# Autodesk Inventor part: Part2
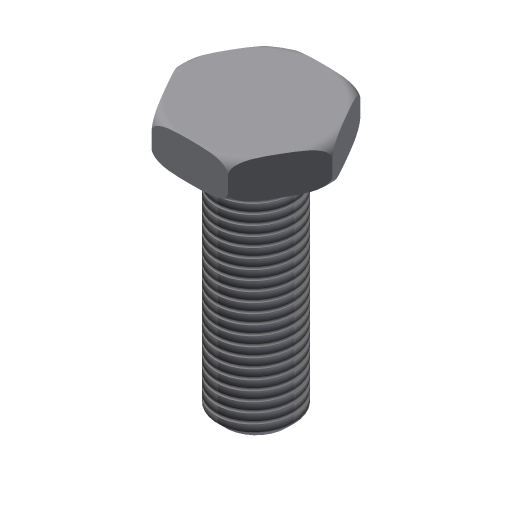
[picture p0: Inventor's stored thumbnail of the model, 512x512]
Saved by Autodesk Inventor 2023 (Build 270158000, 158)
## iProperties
Created: 2002-01
Part Number: Part2
Document SubType Name: Modeling
Designer: ***
Density: 1 g/cm^3
Material: Generic
Appearance: Default
Control State: 0
Master: False
Checked Out: False
Shininess: 77.0
Angle Display Precision: 2
Document Length Units: 11269
Document Angle Units: 11279
Document Time Units: 11290
Document Mass Units: 11283
Document Length Units Precision: 3
Document Angle Units Precision: 2
Density: 0.0
Volumn: 0.0
Area: 0.0
PropertySet Name: Model Information
Author: ***
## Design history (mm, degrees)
sketch "Sketch1"
  geometry: C1 r 20 at (0, 0)
  constraints: 1 centre point
  dimensions: "d0" = 40 diameter of C1
extrude "Extrusion1" new body sketch "Sketch1" distance "d1" = 10; taper "d2" = 0 deg
fillet "Fillet1" dims "d3" = 3
sketch "Sketch3"
  geometry: L1 (20, 0)-(10, -17.321); L2 (10, -17.321)-(-10, -17.321); L3 (-10, -17.321)-(-20, 0); L4 (-20, 0)-(-10, 17.321); L5 (-10, 17.321)-(10, 17.321); L6 (10, 17.321)-(20, 0); C1 r 17 at (0, 0) reference; 1 further point
  constraints: 12 end point, 1 coincident, 11 other
extrude "Extrusion3" sketch "Sketch3" distance "d7" = 10; taper "d8" = 0 deg
sketch "Sketch2"
  geometry: C1 r 10 at (0, 0); 1 further point
  constraints: 1 centre point, 1 coincident
  dimensions: "d4" = 20 diameter of C1
extrude "Extrusion2" join sketch "Sketch2" distance "d5" = 60; taper "d6" = 0 deg
chamfer "Chamfer1" distance "d9" = 2; stored, may be unused: second distance "d10" = 2, angle "d13" = 45 deg
thread "Thread1" dims "d11" = 10, "d12" = 0
body "Solid1"
